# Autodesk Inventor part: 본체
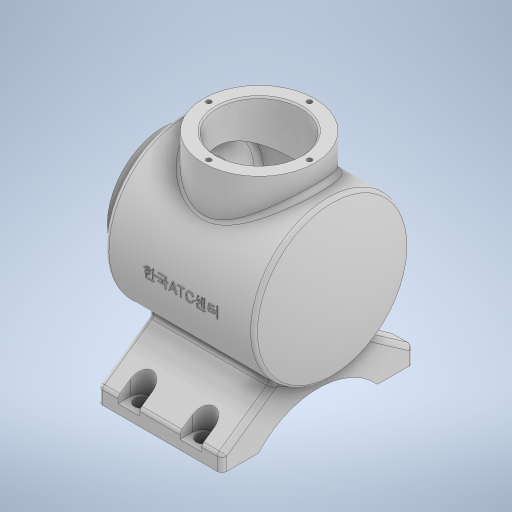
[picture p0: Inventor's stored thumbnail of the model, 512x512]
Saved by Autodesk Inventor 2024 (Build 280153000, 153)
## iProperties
Created: 2023-08
Part Number: 본체
Material: 일반
Document SubType Name: Modeling
Designer: Owner
Density: 1 g/cm^3
Appearance: 기본값
Mass: 480.264 g
Surface Area: 1060.45 cm^2
Volume: 480.264 cm^3
Author: Owner
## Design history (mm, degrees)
sketch "스케치1"
  geometry: L1 (0, 0)-(120, 0); L2 (0, 27)-(0, 36); L3 (0, 36)-(12, 36); L4 (12, 36)-(12, 50); L5 (12, 50)-(108.336, 50); L6 (0, 27)-(19, 27); L7 (19, 27)-(19, 43); L8 (19, 43)-(103.887, 43); A1 r 113 centre (7, 0) between (120, 0) and (108.336, 50); A2 r 106 centre (7, 0) between (113, 0) and (103.887, 43)
  constraints: 16 end point, 5 perpendicular, 4 point on circle, 2 centre point, 2 horizontal, 1 horizontal alignment, 1 point on line, 1 vertical, 1 vertical alignment
  dimensions: "d0" = 120 distance of L1.start L1.end; "d1" = 113 radius of A1; "d2" = 7 radial gap between concentric circles of A1 A2; "d3" = 108 distance from line of L4 L1.end; "d4" = 54 diameter of L6 L1; "d5" = 72 diameter of L3 L1; "d6" = 86 diameter of L8 L1; "d7" = 100 diameter of L5 L1; "d8" = 19 distance of L2.start L6.end
revolve "회전1" sketch "스케치1" stored, may be unused: angle "d9" = 90 deg
node "작업 평면2"
sketch "스케치3"
  geometry: L1 (42.278, -26.694)-(67, -62); L2 (67, -62)-(77, -62); L3 (77, -62)-(77, -38.5); L4 (77, 38.5)-(77, 62); L5 (77, 62)-(67, 62); L6 (67, 62)-(42.278, 26.694); A1 r 50 centre (0, 0) between (42.278, -26.694) and (42.278, 26.694) reference; A2 r 52.096 centre (112.096, 0) between (77, 38.5) and (77, -38.5); 2 further points
  constraints: 12 end point, 5 point on circle, 3 equal length, 2 vertical, 1 centre point, 1 horizontal, 1 horizontal alignment, 1 perpendicular, 1 vertical alignment
  dimensions: "d13" = 77 distance of L4.start L3.end; "d14" = 55 deg angle of L5 L6; "d15" = 10 distance of L4.end L5.end; "d16" = 17 distance from line of point (60, 0) L4; "d17" = 124 distance between parallel lines of L5 L2; "d18" = 77 distance from line of L4 point (0, 0)
extrude "돌출1" join sketch "스케치3" distance "d19" = 80; taper "d20" = 0 deg
node "작업 평면5"
sketch "스케치5"
  geometry: L1 (0, 0)-(80, 0) reference; L2 (67, 0)-(67, 8); L3 (53, 8)-(53, 0); L4 (80, 23.5)-(80, 0) reference; A1 r 7 centre (60, 8) between (67, 8) and (53, 8); 1 further point
  constraints: 4 end point, 2 point on circle, 2 point on line, 2 tangent, 1 centre point, 1 parallel, 1 vertical
  dimensions: "d26" = 14 distance of L3.end L2.start; "d27" = 8 distance from line of A1.centre L1; "d28" = 20 distance from line of A1.centre L4
extrude "돌출2" cut sketch "스케치5" distance "d29" = 33.75; taper "d30" = 0 deg
sketch "스케치6"
  geometry: L1 (53, -8)-(53, 0) reference; L2 (67, 0)-(67, -8) reference; L3 (53, 0)-(67, 0) reference; C1 r 4.5 at (60, -8); A1 r 7 centre (60, -8) between (53, -8) and (67, -8) reference; 1 further point
  constraints: 1 centre point, 1 coincident
  dimensions: "d31" = 9 diameter of C1
extrude "돌출3" cut sketch "스케치6" distance "d32" = 33.75; taper "d33" = 0 deg
node "작업 평면6"
node "작업 평면7"
sketch "스케치7"
  geometry: L1 (-20, -74.5)-(-20, -2.5) reference; C1 r 36 at (42, -38.5); 1 further point
  constraints: 1 centre point, 1 horizontal alignment
  dimensions: "d35" = 72 diameter of C1; "d36" = 62 distance from line of L1 C1.centre
extrude "돌출4" join sketch "스케치7" stored distance "d37" = 33.75; taper "d38" = 0 deg
sketch "스케치8"
  geometry: C1 r 27 at (0, 0); C2 r 36 at (0, 0) reference; 1 further point
  constraints: 1 centre point, 1 coincident, 1 horizontal alignment
  dimensions: "d39" = 54 diameter of C1
extrude "돌출5" cut sketch "스케치8" stored distance "d40" = 10; taper "d41" = 0 deg
fillet "모깎기1" dims "d42" = 3
fillet "모깎기2" dims "d43" = 3
fillet "모깎기3" dims "d44" = 3
fillet "모깎기4" dims "d45" = 3
fillet "모깎기5" dims "d46" = 3
chamfer "모따기1" distance "d47" = 1; stored, may be unused: second distance "d48" = 2, angle "d49" = 45 deg
fillet "모깎기6" dims "d50" = 3
fillet "모깎기7" dims "d51" = 3
fillet "모깎기8" dims "d52" = 3
sketch "스케치9"
  geometry: 2 further points
  constraints: 1 vertical alignment
  dimensions: "d53" = 32.5 distance of point (0, 0) point (0, 32.5)
hole "구멍1" sketch "스케치9" at (0, 32.5) diameter "d54" = 3.242; stored, may be unused: countersink angle "d58" = 90 deg, drill point angle "d60" = 118 deg; dims "d55" = 8, "d56" = 4, "d57" = 2, "d59" = 10
sketch "스케치10"
  geometry: C1 r 36 at (0, 0) reference; C2 r 28 at (0, 0) reference; 2 further points
  constraints: 1 vertical alignment
  dimensions: "d64" = 32.5 distance of C1.centre point (0, 32.5)
hole "구멍2" sketch "스케치10" at (0, 32.5) diameter "d65" = 3.242; stored, may be unused: countersink angle "d69" = 90 deg, drill point angle "d71" = 118 deg; dims "d66" = 8, "d67" = 4, "d68" = 2, "d70" = 10
node "작업 평면8"
sketch "스케치11"
  geometry: 2 further points
  constraints: 1 horizontal alignment, 1 other
  dimensions: "d75" = 62 distance of point (-60.168, 0) point (1.832, 0)
feature "엠보싱1" sketch "스케치11" dims "d13" = 77, "d14" = 55 deg, "d15" = 10, "d16" = 17, "d17" = 124, "d18" = 77, "d76" = 0.5, "d77" = 0
feature "ˁ耀˃耀˅耀ˇ耀ˉ耀ˋ耀ˍ耀ˏ耀" dims "d0" = 120, "d1" = 113, "d2" = 7, "d3" = 108, "d4" = 54, "d5" = 72, "d6" = 86, "d7" = 100, "d8" = 19, "d9" = 90 deg, "d11" = 20, "d13" = 77, "d14" = 55 deg, "d15" = 10, "d16" = 17, "d17" = 124, "d18" = 77, "d19" = 80, "d20" = 0, "d25" = -6, "d26" = 14, "d27" = 8, "d28" = 20, "d29" = 33.75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
node "솔리드1"
mirror "미러1"
mirror "미러2"
pattern_circular "원형 패턴1" dims angle "d62" = 360 deg
pattern_circular "원형 패턴2" dims angle "d73" = 360 deg
node "투영된 루프1"
node "투영된 루프2"
node "투영된 루프3"
feature "A9D066F2-1C7D-4E18-AEED-F7BC21143FA4" dims "d54" = 3.242, "d55" = 8, "d56" = 4, "d57" = 2, "d58" = 90 deg, "d59" = 10, "d60" = 118 deg
